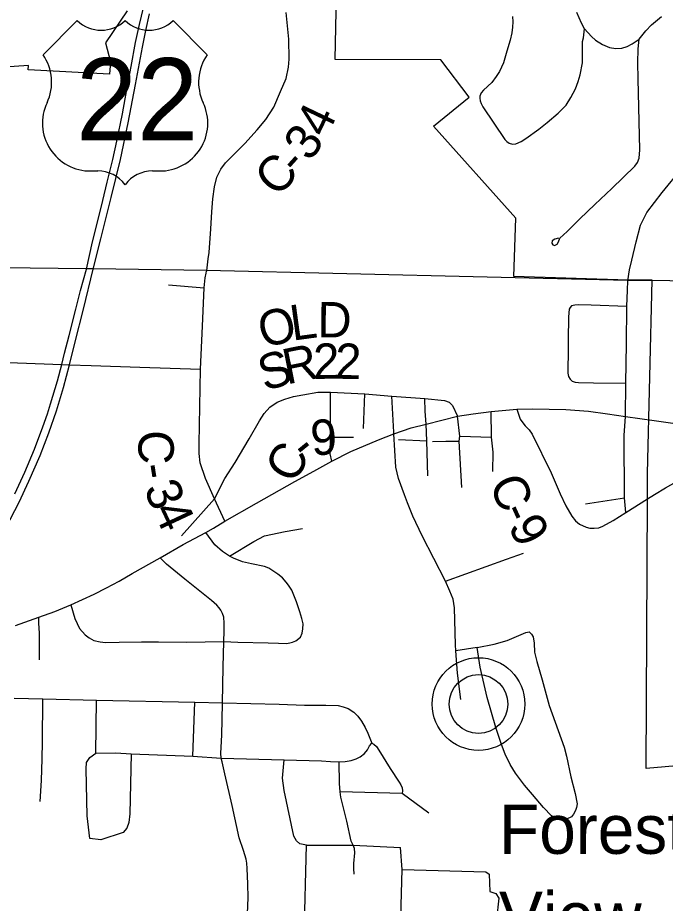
# Model space of a CAD drawing. Extents: x 2402298 to 2498138, y 789485 to 950881.
# Drawn here: x 2459820 to 2465309, y 866330 to 873839 of the extents above; entities that cross this region are included whole.
import ezdxf

# ---------------------------------------------------------------- set-up
doc = ezdxf.new("R2010")
doc.units = 0
for name, color, linetype in [('GM_X_City_Street', 7, 'Continuous'), ('GM_X_Corporation', 7, 'Continuous'), ('GM_X_County_Road', 7, 'Continuous'), ('GM_X_County_Road_Text', 7, 'Continuous'), ('GM_X_Township', 7, 'Continuous'), ('GM_X_Township_Road', 7, 'Continuous'), ('GM_X_Unincorporated', 7, 'Continuous'), ('GM_X_Unincorporated_Text', 7, 'Continuous'), ('GM_X_US_Route', 7, 'Continuous'), ('GM_X_US_Shield', 7, 'Continuous')]:
    doc.layers.add(name, color=color, linetype=linetype)

msp = doc.modelspace()

# ---------------------------------------------------------------- linework, layer by layer
at = {"layer": 'GM_X_City_Street'}
for points in [[(2464012.8, 873850.3), (2464016.7, 873803.3), (2464013.6, 873760), (2464007.5, 873711.3), (2463992.5, 873648), (2463967, 873555.6), (2463937.1, 873455.7), (2463904.2, 873382.2), (2463876.3, 873340), (2463838.9, 873291), (2463768.1, 873225.8), (2463748.2, 873202.2), (2463737.6, 873175.2), (2463736.3, 873155.9), (2463740.2, 873134.1), (2463748.6, 873111.3), (2463761.7, 873082.9), (2463948.2, 872807.7), (2463965.7, 872790.4), (2463986.2, 872775.6), (2464013.6, 872767.7), (2464041.5, 872768.8), (2464086, 872790.2), (2464125.9, 872816.1), (2464237.4, 872895.7), (2464307.7, 872950.8), (2464401.5, 873028.6), (2464468.3, 873097), (2464507.2, 873162.4), (2464546.6, 873236.1), (2464569.9, 873297.9), (2464587.3, 873355.7), (2464608.1, 873458.1), (2464605.9, 873576.9), (2464608.4, 873638.5), (2464616.1, 873668.2), (2464622.2, 873720.3), (2464622.9, 873746.4), (2464598.3, 873793.9), (2464559.8, 873883.8)], [(2464403.7, 871971.1), (2464373.7, 871960.5), (2464350, 871946.9), (2464347.1, 871929), (2464356.3, 871914.5), (2464370.8, 871908.2), (2464391.3, 871919.3), (2464403.2, 871940.2), (2464414.1, 871971.3), (2464476.2, 872025.8), (2464584.1, 872133.1), (2464710.8, 872255), (2464854.5, 872391.9), (2465051.8, 872579.6), (2465073.6, 872613), (2465086.6, 872648.3), (2465092.9, 872720.3), (2465078.4, 873320.6), (2465076, 873456.5), (2465079.8, 873576.9), (2465088.5, 873658.9), (2465142.7, 873727.8), (2465191.1, 873779.1), (2465275.3, 873848.5)], [(2464622.9, 873746.4), (2464683.9, 873681.4), (2464717.2, 873650.2), (2464777.1, 873611.7), (2464835.8, 873587.1), (2464890.1, 873577.6), (2464941.5, 873580.9), (2464985.9, 873595.2), (2465026.6, 873617.2), (2465088.5, 873658.9)], [(2464989.9, 871609.3), (2465004.9, 871702.2), (2465024.7, 871783.4), (2465062.9, 871937.7), (2465098.2, 872079), (2465150.9, 872186.4), (2465282.5, 872357.1), (2465447.9, 872560.7), (2465581.4, 872646.8), (2465702.8, 872720.3), (2465866.3, 872817.6)]]:
    msp.add_lwpolyline(points, dxfattribs=at)
at = {"layer": 'GM_X_Corporation'}
for points in [[(2469460.8, 867584.1), (2469177.1, 867578.6), (2469170.2, 867650.6), (2468202.7, 867668.4), (2467503.1, 867699.8), (2466990.2, 867651.2), (2466335.7, 867576.8), (2465146.1, 867473.5), (2465156.8, 869762.8), (2465157.8, 869974.7), (2465196.7, 871613), (2464995.1, 871612.5), (2464026.3, 871645.6), (2464043.2, 872140.6), (2463344.2, 872919.5), (2463647.3, 873166.8), (2463406.4, 873483.1), (2462511.5, 873484.8), (2462527.1, 874308.5)], [(2460746.4, 873897.9), (2460563.5, 873627.2), (2460606.9, 873465), (2460597.7, 873359.9), (2459907.7, 873396.5), (2459910.3, 873433.3), (2459295.2, 873390.7)]]:
    msp.add_lwpolyline(points, dxfattribs=at)
at = {"layer": 'GM_X_County_Road'}
for points in [[(2461420.7, 871688.8), (2461421.8, 871693.9), (2461433.3, 871794.6), (2461441.2, 871848.1), (2461457.2, 872049.3), (2461465.1, 872192.6), (2461474.2, 872304.1), (2461486.7, 872405.3), (2461508.3, 872488.3), (2461542.5, 872554.3), (2461582.3, 872607.8), (2461744.9, 872773.8), (2461848.4, 872887.6), (2461922.3, 872976.2), (2461990.6, 873080.9), (2462047.4, 873215.1), (2462095.2, 873323.1), (2462114.5, 873419.8), (2462121.4, 873489.2), (2462117.9, 873657.5), (2462095.2, 873885)], [(2461574.7, 869569.2), (2461488.2, 869759), (2461410.4, 869932.1), (2461366, 870064.9), (2461359.2, 870144.6), (2461359.2, 870226.9), (2461370, 870858.5), (2461385.5, 871223.7), (2461401.4, 871548.9), (2461409.4, 871633.1), (2461417.6, 871673.6), (2461420.7, 871688.8)], [(2461209.2, 869446.5), (2461488.2, 869759), (2461575.8, 869932.3), (2461663.8, 870068.4), (2461781.6, 870267.2), (2461870.3, 870421.1), (2461907.4, 870482.7), (2461956, 870535.8), (2462017.7, 870580.2), (2462084.2, 870605.2), (2462157, 870626.1), (2462237.8, 870642.9), (2462362.8, 870663.7), (2462471.9, 870664.9), (2462761, 870651.2), (2462989.5, 870631.3), (2463271, 870609.5), (2463438.5, 870593.6), (2463477.8, 870580), (2463505.8, 870550.5), (2463547.3, 870459.5)], [(2463547.3, 870459.5), (2463679, 870480.4), (2463832, 870499.3), (2464051.7, 870519.8)], [(2464051.7, 870519.8), (2464182.3, 870522.5), (2464465.2, 870516.4), (2464658.8, 870502.2), (2464819.9, 870480.5), (2464970.2, 870458.9)], [(2464051.7, 870519.8), (2464078.5, 870434), (2464091.9, 870414.2), (2464122.1, 870380), (2464154.5, 870344.5), (2464181.7, 870308.3), (2464340.3, 869980.2), (2464416.3, 869801.7), (2464465.3, 869699.1), (2464516, 869614), (2464547.1, 869574.4), (2464580.7, 869543.9), (2464637.2, 869518.2), (2464668.6, 869511.1), (2464705.5, 869509.8), (2464745.4, 869514.2), (2464780, 869528.7), (2464865.6, 869576.1), (2464974.7, 869643.7), (2465157.8, 869760), (2465216, 869795.5)], [(2461574.7, 869569.2), (2461843.7, 869722.8), (2462168.3, 869907.9), (2462329.3, 869993.8), (2462482, 870079.8), (2462644.5, 870161.7), (2462876.6, 870260.6), (2463008.5, 870309.6), (2463155.5, 870362.1), (2463280.7, 870393.2), (2463547.3, 870459.5)], [(2464970.2, 870458.9), (2465215.2, 870424.4), (2465372.5, 870402.3)], [(2465216, 869795.5), (2465309.9, 869852.9), (2465400.6, 869903.3), (2465486.3, 869946), (2465580, 869983.9), (2465741, 870034.2), (2465871.7, 870056), (2465974.3, 870069.9), (2466050.1, 870077), (2466136.7, 870080.7), (2466270.7, 870081.4), (2466389.2, 870077), (2466721.2, 870070.4), (2466791.3, 870076.3), (2466843.5, 870086.3), (2466934.4, 870108.3), (2467022.4, 870125.2), (2467043.7, 870125.5)], [(2461414.9, 869473.9), (2461478.1, 869510.2), (2461574.7, 869569.2)], [(2461027.6, 869259.9), (2461223.2, 869373.3), (2461414.9, 869473.9)], [(2460269.9, 868861.4), (2460370.3, 868905.2), (2460468.6, 868950.8), (2460573.3, 869004.4), (2460679.3, 869062.1), (2460790.6, 869126.5), (2461027.6, 869259.9)], [(2461765.8, 866175.4), (2461772.7, 866376.2), (2461770.4, 866494.3), (2461765, 866626.2), (2461761.6, 866670.3), (2461756.8, 866703.5), (2461733.1, 866776.5), (2461697, 866884.2), (2461638.8, 867157.8), (2461574.9, 867428.3), (2461552.1, 867528.5), (2461543.8, 867561.8), (2461542.7, 867602.5), (2461542.9, 867651.9), (2461548.6, 867759.2), (2461553.8, 867885.1), (2461555.3, 868029.1), (2461560.2, 868333), (2461566, 868548.7), (2461569.9, 868637.9), (2461569.5, 868706), (2461565.9, 868754.8), (2461556.5, 868787.8), (2461542.4, 868816.6), (2461528.6, 868835), (2461508.4, 868857), (2461461.3, 868896.3), (2461236, 869078.1), (2461080.4, 869206.2), (2461027.6, 869259.9)], [(2459800.2, 868684.5), (2459997.8, 868754.9), (2460135, 868805.5), (2460269.9, 868861.4)]]:
    msp.add_lwpolyline(points, dxfattribs=at)
at = {"layer": 'GM_X_Township'}
msp.add_lwpolyline([(2478122.4, 871331.4), (2475264.5, 871386.2), (2475224.5, 871387), (2474415.9, 871412.9), (2474352.1, 871403.7), (2474322.4, 871404.2), (2472192.6, 871453.1), (2469651.1, 871511.4), (2468967.7, 871531.4), (2468934.1, 871536.6), (2468798, 871539.9), (2467941.6, 871563.7), (2467399.3, 871578.7), (2467075, 871587.8), (2466785.7, 871595.8), (2464988.8, 871612.2), (2461420.7, 871696.8), (2460458.8, 871708.7), (2460429.8, 871709.1), (2460401.3, 871709.4), (2459688.5, 871718)], dxfattribs=at)
at = {"layer": 'GM_X_Township_Road'}
for p, q in [((2461096.7, 871575.1), (2461401.4, 871548.9)), ((2462749.7, 870356.2), (2462761, 870651.2)), ((2463007.6, 870325), (2462989.5, 870631.3)), ((2462469.9, 870281.9), (2462665.1, 870283.7)), ((2463566, 870290.9), (2463835, 870282.3)), ((2463046.7, 870261.8), (2463287, 870252.3)), ((2463335.9, 870246), (2463448.9, 870247.6)), ((2463448.9, 870247.6), (2463562, 870249.2)), ((2464633.3, 869717.3), (2464962, 869768.1)), ((2460480.7, 867603.9), (2460486.3, 868053.7)), ((2461304.4, 867578.4), (2461321.5, 868035.8)), ((2462268.9, 866821.8), (2462663.3, 866823.2)), ((2462663.3, 866823.2), (2463064.4, 866803))]:
    msp.add_line(p, q, dxfattribs=at)
for points in [[(2464974.7, 869643.7), (2464962, 869768.1), (2464960.8, 870295.4), (2464970.2, 870458.9), (2464972.9, 870741.3), (2464980.3, 871073.6), (2464981.7, 871391.8), (2464987.1, 871530.4), (2464989.9, 871609.3)], [(2464981.7, 871391.8), (2464679.1, 871400.9), (2464570.5, 871403.6), (2464541, 871402.2), (2464514.6, 871395.1), (2464502.8, 871382.6), (2464494, 871366.7), (2464488.6, 871302.9), (2464485.6, 871108.6), (2464485.5, 870989.7), (2464482.2, 870871.9), (2464483.2, 870825.6), (2464488.6, 870797.1), (2464501.1, 870774.1), (2464519.2, 870758.2), (2464545.8, 870747.7), (2464572.8, 870746), (2464700.1, 870744), (2464972.9, 870741.3)], [(2459620.4, 870919.7), (2459666.5, 870918), (2460193, 870899.1), (2460257.9, 870896), (2460443.5, 870889.5)], [(2460443.5, 870889.5), (2460856.1, 870875), (2461370, 870858.5)], [(2462482, 870079.8), (2462469.1, 870140.3), (2462469.9, 870281.9), (2462471.9, 870664.9)], [(2463294.9, 869953.7), (2463287, 870252.3), (2463280.7, 870393.2), (2463273.1, 870503.7), (2463271, 870609.5)], [(2463584.9, 869856), (2463562, 870249.2), (2463566, 870290.9), (2463547.3, 870459.5)], [(2463846.1, 869991.1), (2463848.4, 870154.2), (2463835, 870282.3), (2463832, 870499.3)], [(2463531.2, 868521.8), (2463522.4, 868836.5), (2463510.3, 868909.9), (2463482, 868977.4), (2463444.7, 869062.7), (2463247.3, 869446.6), (2463168, 869611.7), (2463122.8, 869726.4), (2463099.4, 869794.6), (2463047.1, 869931.5), (2463024.5, 870028.9), (2463008.5, 870309.6), (2463007.6, 870325)], [(2460269.9, 868861.4), (2460304.4, 868744.9), (2460343.1, 868661.4), (2460392.5, 868605.1), (2460425.5, 868580.1), (2460465.7, 868559.5), (2460517.8, 868545.8), (2460564.8, 868541), (2460681.1, 868543.2), (2460869.7, 868546), (2461012.5, 868546.2), (2461251, 868545.6), (2461566, 868548.7), (2461686.8, 868545.3), (2461943.8, 868538.8), (2462031.6, 868535.4), (2462099.3, 868533.5), (2462126.7, 868537.7), (2462148, 868543), (2462177.4, 868555.5), (2462215.7, 868587.5), (2462230.5, 868619.8), (2462237.7, 868655.9), (2462240.2, 868698.5), (2462229.3, 868745.6), (2462211.2, 868802.3), (2462182.2, 868887.3), (2462142, 868984.5), (2462116.1, 869027.5), (2462095.2, 869054.2), (2462062.9, 869090.4), (2462025, 869120.6), (2461989.6, 869144.5), (2461949.5, 869170.6), (2461911.9, 869184.5), (2461800.9, 869208.9), (2461726.3, 869226.1), (2461650.1, 869255.5), (2461616.2, 869273.3), (2461556, 869312.8), (2461489.6, 869370.3), (2461414.9, 869473.9)], [(2461616.2, 869273.3), (2461819.8, 869398.6), (2461912.9, 869445.4), (2462087.2, 869482.9), (2462233.9, 869508.9)], [(2463444.7, 869062.7), (2463961.4, 869248.4), (2464107.1, 869298.8)], [(2460004.9, 868393.5), (2460003.5, 868619.2), (2459997.6, 868704.3), (2459997.8, 868754.9)], [(2463712.9, 868498.1), (2463859.3, 868528.6), (2463967.3, 868559.2), (2464125.7, 868626.5), (2464156, 868632), (2464174.5, 868612.2), (2464189.1, 868589.6), (2464196.9, 868534.4), (2464201.1, 868458.9), (2464218.9, 868379.6), (2464264.1, 868223.6), (2464324.6, 868007.1), (2464450.9, 867653.7), (2464471.8, 867577.7), (2464509.4, 867401.3), (2464545.5, 867259.6), (2464561.5, 867174.5), (2464557.3, 867142.1), (2464548.1, 867115.7), (2464531.9, 867084.9), (2464512.8, 867063.6), (2464471.4, 867044.5), (2464415.3, 867036.7), (2464378.2, 867050), (2464343.1, 867070.3), (2464277.6, 867140.9), (2464183.5, 867251.8), (2464114.3, 867331.5), (2464040.2, 867432.8), (2463994.2, 867507.2), (2463950.7, 867595.3), (2463920.9, 867676.8), (2463871.8, 867820.7), (2463797.9, 868074.3), (2463740.6, 868332.3), (2463712.9, 868498.1), (2463532.6, 868470.2)], [(2463575.2, 868059.2), (2463548.8, 868281.2), (2463532.6, 868470.2), (2463531.2, 868521.8)], [(2459790, 868069.8), (2460033.1, 868062.4), (2460486.3, 868053.7), (2461321.5, 868035.8), (2461555.3, 868029.1)], [(2460011.2, 867192.1), (2460020.2, 867370.9), (2460028.3, 867554.4), (2460030.5, 867699), (2460033.1, 868062.4)], [(2461555.3, 868029.1), (2462036.6, 868017.5), (2462252, 868011.3), (2462432.3, 868009.9), (2462534.6, 868006.9), (2462578.8, 867996.9), (2462621, 867980.4), (2462668.2, 867949.9), (2462702.3, 867916.7), (2462732.5, 867875.2), (2462764.3, 867820.6), (2462787.2, 867773.6), (2462821.3, 867687.4), (2462839.2, 867679.8), (2462859.7, 867659.5), (2462881.4, 867628.6), (2462975.9, 867473.8), (2463052.6, 867357.1), (2463066.9, 867333.8), (2463078.8, 867309.6), (2463080.6, 867284.4), (2463077.8, 867260.5)], [(2462472, 867533), (2462545, 867529.5), (2462596, 867533.1), (2462644.8, 867541.6), (2462687.3, 867555.5), (2462723.7, 867573.1), (2462758.2, 867599.2), (2462785, 867630.4), (2462802.9, 867666.4), (2462821.3, 867687.4)], [(2460781.2, 867598.6), (2460769.1, 867088.8), (2460761.1, 867015), (2460745, 866966.7), (2460712.8, 866929.1), (2460525, 866868.8), (2460431.1, 866878.2), (2460409.6, 867072.7), (2460400.2, 867471.1), (2460404.2, 867524.8), (2460429.7, 867565)], [(2460429.7, 867565), (2460480.7, 867603.9), (2460651.1, 867605.3), (2460781.2, 867598.6), (2461304.4, 867578.4), (2461543.8, 867561.8)], [(2461543.8, 867561.8), (2462078.2, 867545.2), (2462393.8, 867536.8), (2462472, 867533)], [(2463011.7, 864459.6), (2462354.6, 865050), (2462313.5, 865137.2), (2462240.2, 865342.1), (2462213, 865439.4), (2462255.5, 865962.1), (2462247.5, 866043.7), (2462268.9, 866821.8), (2462211.3, 866833.9), (2462181.7, 866860.7), (2462159.5, 866898.2), (2462078.5, 867286.3), (2462065, 867390), (2462078.2, 867545.2)], [(2462663.3, 866823.2), (2462645.9, 866855.7), (2462609.2, 867026), (2462559.6, 867231.1), (2462553.3, 867273.9), (2462546.4, 867347.1), (2462545, 867529.5)], [(2463303.3, 867095.1), (2463077.8, 867260.5), (2462553.3, 867273.9)], [(2462671.4, 866577.7), (2462668.3, 866625.4), (2462668.8, 866666.7), (2462676.7, 866758.8), (2462674.7, 866793.7), (2462663.3, 866823.2)], [(2463046.7, 865920.7), (2463047, 865936.4), (2463045, 866069.9), (2463067.1, 866212.8), (2463079.2, 866616.6), (2463064.4, 866803)], [(2463079.2, 866616.6), (2463788.8, 866597.8), (2463815.7, 866576.3), (2463822.4, 866430.1), (2463873.4, 866414), (2463897.5, 866373.8), (2463878.7, 866191.3), (2463453.5, 866203.4), (2463067.1, 866212.8)]]:
    msp.add_lwpolyline(points, dxfattribs=at)
at = {"layer": 'GM_X_Unincorporated'}
for radius in [392.8, 249]:
    msp.add_circle((2463725.6, 868019.7), radius, dxfattribs=at)
at = {"layer": 'GM_X_US_Route'}
for points in [[(2459795.6, 869802.3), (2459879.8, 869985.3), (2459962.2, 870180.4), (2460033.6, 870371.3), (2460071.7, 870480.6), (2460098.6, 870563.9), (2460157.9, 870760.9), (2460193, 870899.1), (2460217.5, 870994.1), (2460255.6, 871145.3), (2460311.4, 871368.9), (2460350.8, 871526.6), (2460402.4, 871706.6), (2460453.3, 871938.2), (2460492.7, 872093.9), (2460540.4, 872288.7), (2460579.2, 872443.5), (2460625, 872636), (2460659.6, 872793.6), (2460707.4, 873025.6), (2460745.5, 873230.9), (2460781.4, 873426.7), (2460819.2, 873629.5), (2460850.9, 873781.7), (2460886.1, 873924.2)], [(2459718.1, 869514), (2459831.2, 869731.1), (2459914.8, 869909.6), (2460010.2, 870127.8), (2460082.6, 870319.7), (2460147.4, 870505.7), (2460208, 870704.6), (2460257.9, 870896), (2460307.2, 871091.1), (2460376.9, 871367.7), (2460459.9, 871705.9), (2460525.4, 871964.3), (2460612.2, 872313.8), (2460689.9, 872637.6), (2460755.9, 872948), (2460817.5, 873273.9), (2460877.6, 873589.6), (2460904.4, 873731.7), (2460938.1, 873872.7)]]:
    msp.add_lwpolyline(points, dxfattribs=at)
at = {"layer": 'GM_X_US_Shield'}
for p, q in [((2460324.2, 873815.8), (2460034.1, 873525.8)), ((2461426.3, 873525.8), (2461136.3, 873815.8)), ((2460440.2, 872539.7), (2460498.2, 872539.7)), ((2460962.2, 872539.7), (2461020.2, 872539.7))]:
    msp.add_line(p, q, dxfattribs=at)
for centre, radius, start, end in [((2460527.2, 874023), 290, 225.573, 314.427), ((2460933.2, 874023), 290, 225.573, 314.427), ((2459701.5, 873292.9), 406.1, 334.54712, 35.00093), ((2461758.9, 873292.9), 406.1, 144.99907, 205.45288), ((2460435.6, 872945.7), 406.1, 154.83192, 270.63826), ((2461024.8, 872945.7), 406.1, 269.36174, 25.16808), ((2460498.2, 872249.6), 290, 36.8699, 90), ((2460962.2, 872249.6), 290, 90, 143.1301)]:
    msp.add_arc(centre, radius, start, end, dxfattribs=at)

# ---------------------------------------------------------------- texts
at = {"layer": 'GM_X_County_Road_Text'}
for s, rotation, p in [('4', 64.44822, (2462434.3, 872811.8)), ('3', 54.43105, (2462297.7, 872612.2)), ('C', 46.86594, (2462019.2, 872307.5)), ('-', 47.89838, (2462191.6, 872491.7)), ('L', 7.7725, (2462148.5, 871100.1)), ('D', 359.44265, (2462359.3, 871129.7)), ('O', 14.74041, (2461902.7, 871034.8)), ('R', 11.47679, (2462098.8, 870728.4)), ('2', 0.83265, (2462325.7, 870775.8)), ('2', 358.86548, (2462507.7, 870778.5)), ('S', 17.60855, (2461914.1, 870669.3)), ('9', 4.61455, (2462314.2, 870124.7)), ('C', 269.35598, (2460844.3, 870343.3)), ('C', 60.01155, (2462159.4, 869875.3)), ('-', 39.03746, (2462262.9, 870065.2)), ('-', 278.95031, (2460845.5, 870042.3)), ('3', 292.32925, (2460885.3, 869847.1)), ('C', 293.14017, (2463811.3, 869889.8)), ('4', 295.14304, (2460961.9, 869661.4)), ('-', 294.51292, (2463911.3, 869656.1)), ('9', 297.95135, (2463971.1, 869526.3))]:
    msp.add_text(s, height=300, rotation=rotation, dxfattribs=at).set_placement(p)
at = {"layer": 'GM_X_Unincorporated_Text'}
for s, p in [('Forest', (2463899.5, 866749.3)), ('View', (2463899.5, 866010.1))]:
    msp.add_text(s, height=417, rotation=0.00001, dxfattribs=at).set_placement(p)
at = {"layer": 'GM_X_US_Shield'}
msp.add_text('22', height=696.1, dxfattribs=at).set_placement((2460314.3, 872800.7))

doc.saveas('drawing.dxf')
